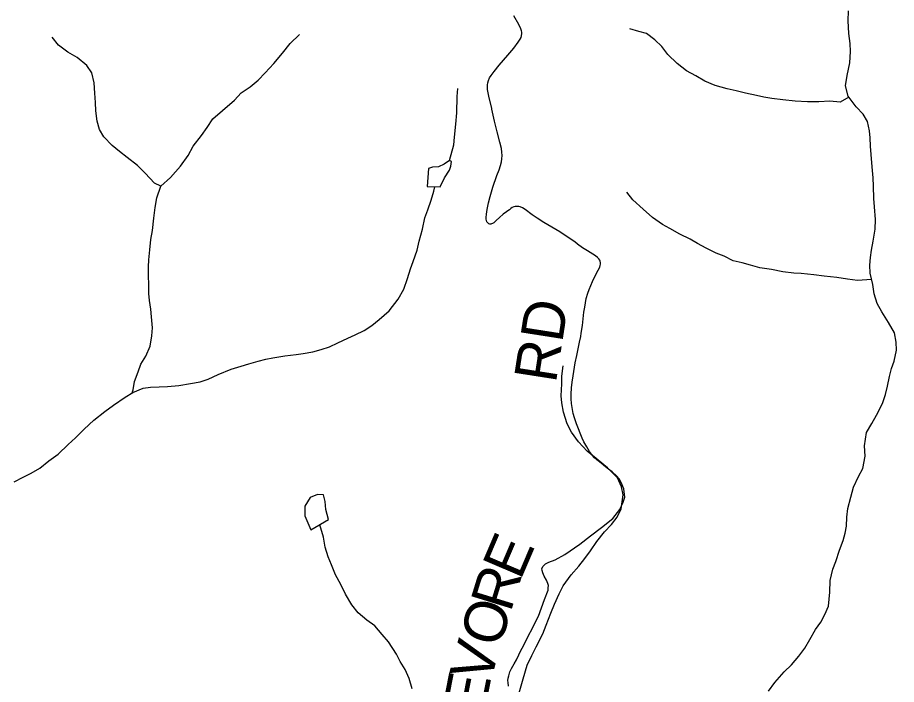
# Model space of a CAD drawing. Extents: x 0 to 34, y 0 to 22.
# Drawn here: x 6.068 to 7.245, y 16.003 to 16.898 of the extents above; entities that cross this region are included whole.
import ezdxf

# ---------------------------------------------------------------- set-up
doc = ezdxf.new("R2010")
doc.units = 0
for name, color, linetype in [('GM_X_Minor_Lake', 7, 'Continuous'), ('GM_X_Minor_River', 7, 'Continuous'), ('GM_X_Township_Road', 7, 'Continuous'), ('GM_X_Township_Road_Text', 7, 'Continuous')]:
    doc.layers.add(name, color=color, linetype=linetype)

msp = doc.modelspace()

# ---------------------------------------------------------------- linework, layer by layer
at = {"layer": 'GM_X_Minor_Lake'}
for points in [[(6.6336, 16.6704), (6.6395, 16.6825), (6.6461, 16.693), (6.648, 16.6983), (6.6489, 16.7044), (6.6462, 16.7059), (6.6393, 16.7011), (6.6317, 16.6974), (6.6237, 16.6971), (6.6184, 16.6949), (6.6165, 16.671)], [(6.6165, 16.671), (6.6336, 16.6704)], [(6.4842, 16.2243), (6.4806, 16.238), (6.4796, 16.2487), (6.4774, 16.2575), (6.4695, 16.258), (6.4596, 16.2539), (6.4526, 16.2423), (6.4524, 16.2293), (6.4605, 16.2106)], [(6.4605, 16.2106), (6.4842, 16.2243)]]:
    msp.add_lwpolyline(points, dxfattribs=at)
at = {"layer": 'GM_X_Minor_River'}
for points in [[(7.0738, 15.9945), (7.0823, 16.0061), (7.0947, 16.02), (7.1043, 16.0298), (7.1143, 16.0414), (7.1224, 16.0519), (7.1291, 16.0636), (7.1365, 16.0768), (7.1438, 16.0869), (7.1493, 16.0971), (7.154, 16.1084), (7.1558, 16.127), (7.1564, 16.1426), (7.16, 16.1577), (7.164, 16.1683), (7.1687, 16.1834), (7.1735, 16.1963), (7.1766, 16.2061), (7.1783, 16.2156), (7.1788, 16.2277), (7.1801, 16.2391), (7.1838, 16.2546), (7.1874, 16.2679), (7.1944, 16.2822), (7.1999, 16.2927), (7.2032, 16.3094), (7.2022, 16.3231), (7.2051, 16.3413), (7.2121, 16.3533), (7.2184, 16.3643), (7.2266, 16.3801), (7.2305, 16.3922), (7.233, 16.4032), (7.2358, 16.4164), (7.2386, 16.427), (7.2418, 16.4369), (7.245, 16.4516), (7.2448, 16.4623), (7.2424, 16.4748), (7.2346, 16.4886), (7.2257, 16.5028), (7.2194, 16.5139), (7.2154, 16.5269), (7.2133, 16.5395), (7.2098, 16.5547), (7.2095, 16.5657), (7.2101, 16.576), (7.2117, 16.5858), (7.2138, 16.5976), (7.2167, 16.6139), (7.2169, 16.6268), (7.2156, 16.6435), (7.2146, 16.6549), (7.2145, 16.6716), (7.2139, 16.6827), (7.2126, 16.6975), (7.2113, 16.7139), (7.2103, 16.7249), (7.2098, 16.7363), (7.2091, 16.7458), (7.2063, 16.758), (7.2004, 16.768), (7.191, 16.7776), (7.1802, 16.7922), (7.177, 16.8059), (7.1791, 16.8196), (7.1828, 16.8366), (7.1834, 16.8518), (7.1832, 16.8628), (7.1815, 16.8761), (7.1806, 16.8929), (7.1808, 16.9065)], [(6.2212, 16.3945), (6.2224, 16.3984), (6.2245, 16.4093), (6.2292, 16.4226), (6.2328, 16.4328), (6.2394, 16.4437), (6.2453, 16.4569), (6.2477, 16.4709), (6.2483, 16.4816), (6.247, 16.4964), (6.246, 16.5063), (6.2446, 16.5181), (6.2436, 16.5276), (6.2434, 16.5398), (6.2432, 16.5512), (6.243, 16.5633), (6.2435, 16.5728), (6.2449, 16.5861), (6.2462, 16.6001), (6.2486, 16.6122), (6.25, 16.6286), (6.2518, 16.643), (6.2542, 16.6558), (6.2594, 16.6713), (6.2724, 16.6829), (6.2859, 16.6983), (6.296, 16.7126), (6.303, 16.725), (6.3142, 16.7393), (6.3216, 16.7502), (6.3293, 16.7615), (6.3424, 16.7731), (6.3581, 16.7869), (6.3674, 16.7967), (6.3792, 16.8048), (6.39, 16.8134), (6.3992, 16.8232), (6.4108, 16.8359), (6.4224, 16.8498), (6.4328, 16.8626), (6.4455, 16.8749)], [(7.1814, 16.7907), (7.1695, 16.784), (7.1559, 16.7853), (7.1411, 16.7844), (7.1259, 16.7843), (7.1096, 16.7853), (7.0929, 16.787), (7.0782, 16.7891), (7.0676, 16.7908), (7.0578, 16.7932), (7.043, 16.7961), (7.0302, 16.7994), (7.0185, 16.8018), (7.0022, 16.8062), (6.9883, 16.8121), (6.9762, 16.8192), (6.9638, 16.8262), (6.9511, 16.8359), (6.9387, 16.8478), (6.9309, 16.8586), (6.9212, 16.8678), (6.9103, 16.876), (6.9001, 16.8788), (6.8881, 16.8824)], [(6.2594, 16.6713), (6.2511, 16.6753), (6.2384, 16.6887), (6.2283, 16.6992), (6.2144, 16.71), (6.2043, 16.7177), (6.1946, 16.7259), (6.1834, 16.7378), (6.1774, 16.7474), (6.1742, 16.7588), (6.1725, 16.7725), (6.1719, 16.7836), (6.1713, 16.7961), (6.1704, 16.8102), (6.1672, 16.8235), (6.1605, 16.8331), (6.1474, 16.8439), (6.135, 16.8513), (6.1226, 16.8606), (6.114, 16.8714)], [(6.6463, 16.7059), (6.6519, 16.7267), (6.6531, 16.737), (6.6549, 16.7544), (6.6563, 16.7696), (6.6566, 16.7916), (6.6575, 16.8026)], [(6.0633, 16.2749), (6.0751, 16.2812), (6.0858, 16.2864), (6.0977, 16.2934), (6.1095, 16.3031), (6.1222, 16.3121), (6.1353, 16.3252), (6.1453, 16.3338), (6.1568, 16.3457), (6.1699, 16.3577), (6.1845, 16.3693), (6.1963, 16.3778), (6.2117, 16.3886), (6.222, 16.3949), (6.2361, 16.4008), (6.2456, 16.4018), (6.2574, 16.4024), (6.2687, 16.403), (6.2835, 16.4043), (6.2995, 16.4067), (6.3121, 16.4092), (6.3231, 16.4125), (6.3365, 16.4187), (6.354, 16.4261), (6.367, 16.43), (6.3776, 16.4333), (6.3902, 16.4369), (6.4001, 16.4394), (6.4096, 16.4412), (6.4259, 16.444), (6.4407, 16.4457), (6.4502, 16.4471), (6.4632, 16.4495), (6.4746, 16.4524), (6.4856, 16.456), (6.4967, 16.4612), (6.5101, 16.4678), (6.52, 16.4722), (6.5318, 16.4781), (6.5422, 16.4848), (6.5521, 16.4927), (6.5656, 16.5042), (6.5776, 16.52), (6.585, 16.5332), (6.5901, 16.5476), (6.5941, 16.5604), (6.5976, 16.5706), (6.6028, 16.5857), (6.6056, 16.5979), (6.61, 16.6138), (6.6133, 16.6289), (6.6172, 16.6395), (6.6216, 16.6527), (6.6255, 16.6648), (6.6266, 16.6706)], [(7.2118, 16.5461), (7.1929, 16.5451), (7.1797, 16.5468), (7.1653, 16.5489), (7.1483, 16.5507), (7.1343, 16.5524), (7.1176, 16.5542), (7.1078, 16.5547), (7.093, 16.5564), (7.0775, 16.5597), (7.062, 16.5618), (7.0495, 16.5654), (7.0382, 16.5686), (7.0265, 16.5715), (7.0141, 16.5774), (7.0035, 16.5817), (6.9903, 16.5884), (6.9787, 16.5946), (6.9689, 16.6004), (6.955, 16.6071), (6.9414, 16.6145), (6.9316, 16.62), (6.9181, 16.6293), (6.9058, 16.6405), (6.8919, 16.6533), (6.8837, 16.6636)], [(6.7397, 15.9922), (6.7449, 16.0108), (6.7505, 16.0293), (6.7568, 16.0421), (6.7626, 16.0538), (6.7712, 16.0712), (6.7756, 16.0829), (6.7822, 16.0987), (6.787, 16.1108), (6.7932, 16.1248), (6.7987, 16.1357), (6.8095, 16.1504), (6.8196, 16.162), (6.8277, 16.1721), (6.8354, 16.1823), (6.8436, 16.1951), (6.854, 16.2078), (6.8632, 16.2179), (6.871, 16.2277), (6.8764, 16.239), (6.879, 16.2576), (6.8769, 16.2683), (6.8713, 16.2805), (6.8579, 16.2936), (6.8429, 16.3064), (6.8309, 16.3161), (6.819, 16.3284), (6.8097, 16.3414), (6.8041, 16.3529), (6.7991, 16.3682), (6.7966, 16.3808), (6.796, 16.3903), (6.7966, 16.4066), (6.7967, 16.4165), (6.7988, 16.4305)], [(6.5965, 15.9974), (6.5921, 16.0111), (6.587, 16.0234), (6.5804, 16.0341), (6.5752, 16.0437), (6.5644, 16.0605), (6.5562, 16.0705), (6.5462, 16.0817), (6.5357, 16.0895), (6.524, 16.0995), (6.5155, 16.1099), (6.507, 16.1244), (6.5007, 16.1371), (6.4937, 16.1501), (6.4882, 16.1635), (6.4838, 16.1746), (6.4798, 16.1875), (6.4774, 16.2009), (6.4724, 16.2175)]]:
    msp.add_lwpolyline(points, dxfattribs=at)
at = {"layer": 'GM_X_Township_Road'}
msp.add_lwpolyline([(6.7255, 16.0011), (6.7247, 16.006), (6.7246, 16.0088), (6.7249, 16.0116), (6.7256, 16.015), (6.7273, 16.02), (6.7293, 16.0245), (6.733, 16.0309), (6.7359, 16.0362), (6.739, 16.0432), (6.7413, 16.0478), (6.7437, 16.0518), (6.7657, 16.095), (6.7738, 16.1173), (6.7783, 16.1296), (6.7787, 16.1329), (6.7789, 16.1359), (6.7781, 16.1387), (6.7763, 16.143), (6.7733, 16.1484), (6.7712, 16.1528), (6.7704, 16.1562), (6.7701, 16.1589), (6.7716, 16.1617), (6.7749, 16.1649), (6.7793, 16.1672), (6.7879, 16.1706), (6.8006, 16.1774), (6.8208, 16.1913), (6.8352, 16.2024), (6.8501, 16.2138), (6.865, 16.2257), (6.8747, 16.2378), (6.879, 16.2475), (6.8812, 16.2545), (6.88, 16.2657), (6.8762, 16.274), (6.8735, 16.2788), (6.8703, 16.2827), (6.8644, 16.2882), (6.8595, 16.2921), (6.8555, 16.2949), (6.8497, 16.3001), (6.8439, 16.3044), (6.8407, 16.3072), (6.8379, 16.3103), (6.834, 16.3158), (6.8301, 16.3219), (6.8263, 16.3287), (6.824, 16.3336), (6.8165, 16.3526), (6.8137, 16.3607), (6.812, 16.3667), (6.8109, 16.3721), (6.8097, 16.3801), (6.8092, 16.3863), (6.8091, 16.3925), (6.8097, 16.4011), (6.8105, 16.4085), (6.8121, 16.4169), (6.8148, 16.4344), (6.8167, 16.4446), (6.8206, 16.4621), (6.8223, 16.4699), (6.8229, 16.4742), (6.8244, 16.4846), (6.8253, 16.4935), (6.8263, 16.5026), (6.8274, 16.5094), (6.8296, 16.5206), (6.8315, 16.5279), (6.8332, 16.5328), (6.838, 16.5435), (6.8429, 16.5537), (6.8457, 16.5589), (6.8475, 16.5629), (6.8483, 16.5652), (6.8486, 16.567), (6.8486, 16.5688), (6.8483, 16.5707), (6.8475, 16.5724), (6.8465, 16.5739), (6.8448, 16.5757), (6.8418, 16.5779), (6.8313, 16.5846), (6.8245, 16.5889), (6.818, 16.5937), (6.814, 16.5966), (6.8014, 16.6055), (6.7941, 16.6103), (6.7728, 16.6229), (6.7637, 16.6284), (6.757, 16.6329), (6.7476, 16.64), (6.744, 16.6424), (6.7411, 16.6436), (6.7393, 16.6441), (6.7369, 16.6443), (6.7344, 16.6443), (6.7327, 16.6438), (6.7304, 16.6428), (6.7284, 16.6414), (6.7265, 16.6398), (6.7245, 16.6384), (6.7227, 16.6371), (6.7184, 16.6337), (6.7132, 16.6294), (6.7087, 16.6252), (6.7055, 16.6222), (6.7039, 16.6212), (6.7028, 16.6208), (6.7016, 16.6206), (6.7003, 16.6206), (6.6992, 16.621), (6.6981, 16.6217), (6.6972, 16.6226), (6.6965, 16.6236), (6.6959, 16.6253), (6.6955, 16.6271), (6.6955, 16.6296), (6.6958, 16.634), (6.6967, 16.6401), (6.6984, 16.6492), (6.7006, 16.6577), (6.7045, 16.6701), (6.7099, 16.6858), (6.7127, 16.6934), (6.7148, 16.6992), (6.716, 16.704), (6.7166, 16.7083), (6.7168, 16.7127), (6.7165, 16.717), (6.7158, 16.7219), (6.7139, 16.7303), (6.7102, 16.7441), (6.7066, 16.7585), (6.7029, 16.7748), (6.703, 16.7755), (6.699, 16.7922), (6.6974, 16.8009), (6.6971, 16.804), (6.6973, 16.8071), (6.6978, 16.8102), (6.6986, 16.8132), (6.7001, 16.8166), (6.702, 16.8198), (6.706, 16.8253), (6.7127, 16.8335), (6.7246, 16.847), (6.7325, 16.8565), (6.7385, 16.8644), (6.7412, 16.8686), (6.7422, 16.8708), (6.7429, 16.8732), (6.7433, 16.8762), (6.7433, 16.8781), (6.7429, 16.8799), (6.742, 16.8822), (6.739, 16.8883), (6.7326, 16.8996)], dxfattribs=at)

# ---------------------------------------------------------------- texts
at = {"layer": 'GM_X_Township_Road_Text'}
for s, height, rotation, p in [('RD', 0.05682, 81.1071, (6.7887, 16.4062)), ('E', 0.0568, 66.8543, (6.7413, 16.142)), ('R', 0.0568, 72.8938, (6.7281, 16.0989)), ('O', 0.0568, 72.968, (6.7135, 16.0511)), ('V', 0.0568, 74.856, (6.7006, 16.0033)), ('E', 0.0568, 78.9302, (6.6927, 15.9627))]:
    msp.add_text(s, height=height, rotation=rotation, dxfattribs=at).set_placement(p)

doc.saveas('drawing.dxf')
